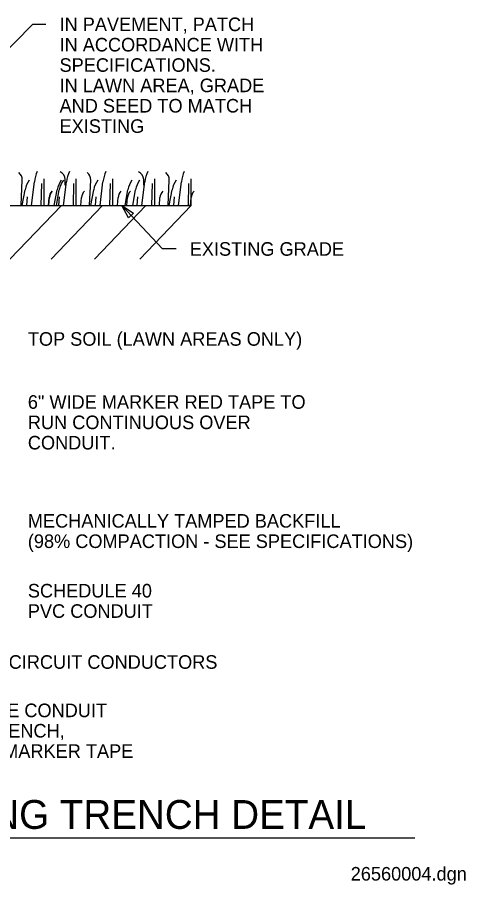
# Model space of a CAD drawing. Extents: x 10111 to 10157.2, y 10072.4 to 10116.1.
# Drawn here: x 10135.23 to 10157.25, y 10072.42 to 10115.03 of the extents above; entities that cross this region are included whole.
import ezdxf

# ---------------------------------------------------------------- set-up
doc = ezdxf.new("R2010")
doc.units = 0
for name, color, linetype in [('G-ANNO-TEXT', 7, 'Continuous'), ('G-DETL-LINE', 7, 'Continuous'), ('G-DETL-PATT', 7, 'Continuous')]:
    doc.layers.add(name, color=color, linetype=linetype)

msp = doc.modelspace()

# ---------------------------------------------------------------- linework, layer by layer
at = {"layer": 'G-ANNO-TEXT'}
for p, q in [((10135.967, 10114.69), (10132.554, 10111.19)), ((10136.634, 10114.69), (10135.967, 10114.69)), ((10142.362, 10103.655), (10140.358, 10105.783)), ((10143.029, 10103.655), (10142.362, 10103.655)), ((10114.344, 10074.731), (10154.756, 10074.731))]:
    msp.add_line(p, q, dxfattribs=at)
msp.add_lwpolyline([(10140.693, 10105.184), (10140.358, 10105.783), (10140.936, 10105.412)], close=True, dxfattribs=at)
at = {"layer": 'G-DETL-LINE'}
msp.add_line((10110.977, 10105.793), (10143.768, 10105.793), dxfattribs=at)
at = {"layer": 'G-DETL-PATT'}
for p, q in [((10137.389, 10105.791), (10134.857, 10103.156)), ((10139.414, 10105.791), (10136.883, 10103.156)), ((10141.541, 10105.791), (10139.009, 10103.156)), ((10143.769, 10105.791), (10141.237, 10103.156))]:
    msp.add_line(p, q, dxfattribs=at)
for points in [[(10135.408, 10105.814), (10135.465, 10107.04)], [(10136.548, 10105.793), (10136.548, 10107.097)], [(10137.582, 10106.783), (10137.582, 10107.068)], [(10138.123, 10105.793), (10138.123, 10107.097)], [(10138.778, 10105.814), (10138.835, 10107.04)], [(10139.917, 10105.793), (10139.917, 10107.097)], [(10141.433, 10106.783), (10141.433, 10107.068)], [(10141.974, 10105.793), (10141.974, 10107.097)], [(10142.629, 10105.814), (10142.686, 10107.04)], [(10143.768, 10105.793), (10143.768, 10107.097)], [(10135.921, 10105.793), (10136.063, 10106.954)], [(10136.405, 10105.793), (10136.434, 10106.869)], [(10137.497, 10105.793), (10137.639, 10106.954)], [(10137.981, 10105.793), (10138.009, 10106.869)], [(10139.291, 10105.793), (10139.433, 10106.954)], [(10139.775, 10105.793), (10139.803, 10106.869)], [(10141.348, 10105.793), (10141.49, 10106.954)], [(10141.832, 10105.793), (10141.86, 10106.869)], [(10143.142, 10105.793), (10143.284, 10106.954)], [(10143.626, 10105.793), (10143.654, 10106.869)], [(10135.465, 10105.793), (10135.608, 10106.555)], [(10135.693, 10105.793), (10135.722, 10106.213)], [(10136.756, 10105.793), (10136.785, 10106.185)], [(10136.775, 10105.793), (10136.804, 10106.185)], [(10137.041, 10105.793), (10137.183, 10106.555)], [(10137.146, 10105.793), (10137.288, 10106.555)], [(10137.269, 10105.793), (10137.297, 10106.213)], [(10138.351, 10105.793), (10138.379, 10106.185)], [(10138.835, 10105.793), (10138.977, 10106.555)], [(10139.063, 10105.793), (10139.091, 10106.213)], [(10140.145, 10105.793), (10140.174, 10106.185)], [(10140.515, 10105.793), (10140.658, 10106.555)], [(10140.607, 10105.793), (10140.636, 10106.185)], [(10140.892, 10105.793), (10141.034, 10106.555)], [(10141.12, 10105.793), (10141.148, 10106.213)], [(10142.202, 10105.793), (10142.231, 10106.185)], [(10142.686, 10105.793), (10142.829, 10106.555)], [(10142.914, 10105.793), (10142.942, 10106.213)], [(10143.736, 10105.793), (10143.765, 10106.185)]]:
    msp.add_lwpolyline(points, dxfattribs=at)
for centre, radius, start, end in [((10137.846, 10106.736), 1.796, 155.9651, 173.0105), ((10139.422, 10106.736), 1.796, 155.9651, 173.0105), ((10141.216, 10106.736), 1.796, 155.9651, 173.0105), ((10143.273, 10106.736), 1.796, 155.9651, 173.0105), ((10145.067, 10106.736), 1.796, 155.9651, 173.0105), ((10135.023, 10107.06), 0.443, 357.3391, 52.176), ((10136.869, 10106.32), 1.283, 145.8509, 169.4213), ((10138.444, 10106.32), 1.283, 145.8509, 169.4213), ((10138.549, 10106.32), 1.283, 145.8509, 169.4213), ((10137.186, 10107.068), 0.396, 0, 69.3471), ((10138.392, 10107.06), 0.443, 357.3391, 52.176), ((10140.238, 10106.32), 1.283, 145.8509, 169.4213), ((10141.919, 10106.32), 1.283, 145.8509, 169.4213), ((10142.295, 10106.32), 1.283, 145.8509, 169.4213), ((10141.037, 10107.068), 0.396, 0, 69.3471), ((10142.244, 10107.06), 0.443, 357.3391, 52.176), ((10144.089, 10106.32), 1.283, 145.8509, 169.4213), ((10137.28, 10106.149), 0.497, 135.303, 175.8439), ((10137.299, 10106.149), 0.497, 135.303, 175.8439), ((10138.875, 10106.149), 0.497, 135.303, 175.8439), ((10140.669, 10106.149), 0.497, 135.303, 175.8439), ((10141.131, 10106.149), 0.497, 135.303, 175.8439), ((10142.726, 10106.149), 0.497, 135.303, 175.8439), ((10144.26, 10106.149), 0.497, 135.303, 175.8439)]:
    msp.add_arc(centre, radius, start, end, dxfattribs=at)

# ---------------------------------------------------------------- texts
at = {"layer": 'G-ANNO-TEXT'}
for s, height, p in [('IN PAVEMENT, PATCH', 0.66667, (10137.3, 10114.357)), ('IN ACCORDANCE WITH', 0.66667, (10137.3, 10113.357)), ('SPECIFICATIONS.', 0.66667, (10137.3, 10112.357)), ('IN LAWN AREA, GRADE ', 0.66667, (10137.3, 10111.357)), ('AND SEED TO MATCH ', 0.66667, (10137.3, 10110.357)), ('EXISTING', 0.6667, (10137.3, 10109.357)), ('EXISTING GRADE', 0.66667, (10143.695, 10103.321)), ('TOP SOIL (LAWN AREAS ONLY)', 0.66667, (10135.743, 10098.9)), ('6" WIDE MARKER RED TAPE TO ', 0.66667, (10135.743, 10095.803)), ('RUN CONTINUOUS OVER', 0.66667, (10135.743, 10094.803)), ('CONDUIT.', 0.6667, (10135.743, 10093.803)), ('MECHANICALLY TAMPED BACKFILL', 0.66667, (10135.743, 10089.963)), ('(98% COMPACTION - SEE SPECIFICATIONS)', 0.66667, (10135.743, 10088.963)), ('SCHEDULE 40 ', 0.66667, (10135.743, 10086.532)), ('PVC CONDUIT', 0.66667, (10135.743, 10085.532)), ('LIGHTING CIRCUIT CONDUCTORS', 0.66667, (10130.344, 10083.029)), ('WHERE MORE THAN ONE CONDUIT', 0.66667, (10124.229, 10080.652)), ('IS INSTALLED IN THE TRENCH,', 0.66667, (10124.229, 10079.652)), ('PROVIDE THE PROPER MARKER TAPE', 0.66667, (10124.229, 10078.652)), ('TYPICAL SITE LIGHTING TRENCH DETAIL', 1.41667, (10114.681, 10075.164)), ('26560004.dgn', 0.66667, (10151.601, 10072.625))]:
    msp.add_text(s, height=height, dxfattribs=at).set_placement(p)

doc.saveas('drawing.dxf')
